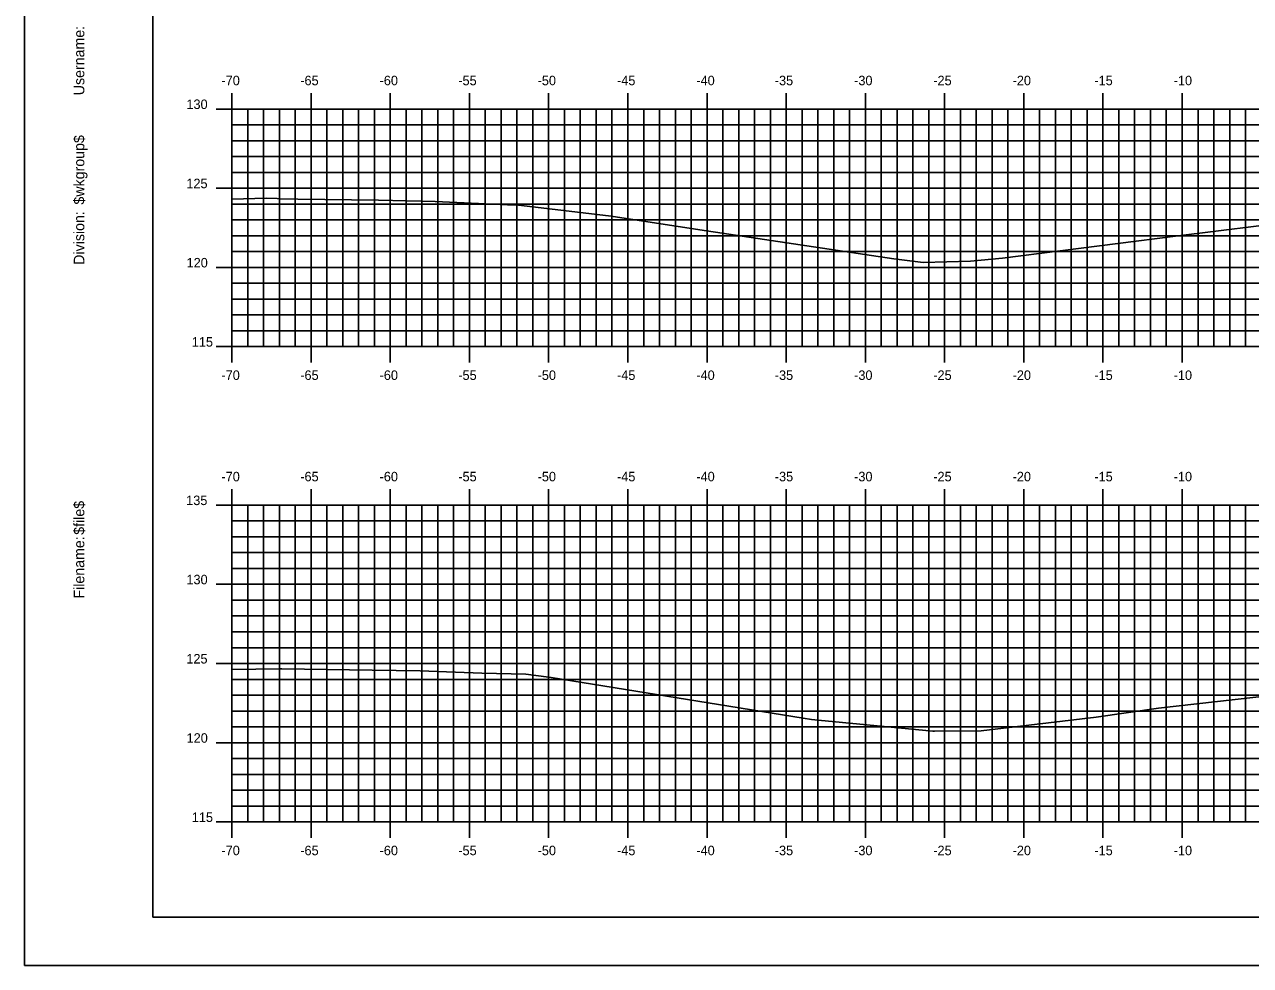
# Model space of a CAD drawing. Extents: x 852182 to 852354, y 365624 to 365734.
# Drawn here: x 852181.9 to 852259.3, y 365624 to 365683.4 of the extents above; entities that cross this region are included whole.
import ezdxf

# ---------------------------------------------------------------- set-up
doc = ezdxf.new("R2010")
doc.units = 0
for name, color, linetype in [('BORDER', 7, 'Continuous'), ('H_V ANNOTATION', 7, 'Continuous'), ('M_Roadway_Centerline', 7, 'Continuous'), ('MAJOR', 7, 'Continuous'), ('MINOR', 7, 'Continuous'), ('PLOT BOUNDARY', 7, 'Continuous'), ('S_Roadway_Centerline', 7, 'Continuous')]:
    doc.layers.add(name, color=color, linetype=linetype)

msp = doc.modelspace()

# ---------------------------------------------------------------- linework, layer by layer
at = {"layer": 'BORDER'}
msp.add_lwpolyline([(852190.035, 365627.027), (852350.035, 365627.027), (852350.035, 365732.027), (852190.035, 365732.027)], close=True, dxfattribs=at)
at = {"layer": 'MAJOR'}
for p, q in [((852195.035, 365679.029), (852195.035, 365678.027)), ((852200.035, 365679.029), (852200.035, 365678.027)), ((852205.035, 365679.029), (852205.035, 365678.027)), ((852210.035, 365679.029), (852210.035, 365678.027)), ((852215.035, 365679.029), (852215.035, 365678.027)), ((852220.035, 365679.029), (852220.035, 365678.027)), ((852225.035, 365679.029), (852225.035, 365678.027)), ((852230.035, 365679.029), (852230.035, 365678.027)), ((852235.035, 365679.029), (852235.035, 365678.027)), ((852240.035, 365679.029), (852240.035, 365678.027)), ((852245.035, 365679.029), (852245.035, 365678.027)), ((852250.035, 365679.029), (852250.035, 365678.027)), ((852255.035, 365679.029), (852255.035, 365678.027)), ((852194.033, 365678.027), (852195.035, 365678.027)), ((852195.035, 365678.027), (852335.035, 365678.027)), ((852195.035, 365663.027), (852195.035, 365678.027)), ((852195.035, 365663.027), (852195.035, 365678.027)), ((852195.035, 365678.027), (852335.035, 365678.027)), ((852200.035, 365663.027), (852200.035, 365678.027)), ((852205.035, 365663.027), (852205.035, 365678.027)), ((852210.035, 365663.027), (852210.035, 365678.027)), ((852215.035, 365663.027), (852215.035, 365678.027)), ((852220.035, 365663.027), (852220.035, 365678.027)), ((852225.035, 365663.027), (852225.035, 365678.027)), ((852230.035, 365663.027), (852230.035, 365678.027)), ((852235.035, 365663.027), (852235.035, 365678.027)), ((852240.035, 365663.027), (852240.035, 365678.027)), ((852245.035, 365663.027), (852245.035, 365678.027)), ((852250.035, 365663.027), (852250.035, 365678.027)), ((852255.035, 365663.027), (852255.035, 365678.027)), ((852194.033, 365673.027), (852195.035, 365673.027)), ((852195.035, 365673.027), (852335.035, 365673.027)), ((852194.033, 365668.027), (852195.035, 365668.027)), ((852195.035, 365668.027), (852335.035, 365668.027)), ((852194.033, 365663.027), (852195.035, 365663.027)), ((852195.035, 365663.027), (852335.035, 365663.027)), ((852195.035, 365663.027), (852335.035, 365663.027)), ((852195.035, 365662.025), (852195.035, 365663.027)), ((852200.035, 365662.025), (852200.035, 365663.027)), ((852205.035, 365662.025), (852205.035, 365663.027)), ((852210.035, 365662.025), (852210.035, 365663.027)), ((852215.035, 365662.025), (852215.035, 365663.027)), ((852220.035, 365662.025), (852220.035, 365663.027)), ((852225.035, 365662.025), (852225.035, 365663.027)), ((852230.035, 365662.025), (852230.035, 365663.027)), ((852235.035, 365662.025), (852235.035, 365663.027)), ((852240.035, 365662.025), (852240.035, 365663.027)), ((852245.035, 365662.025), (852245.035, 365663.027)), ((852250.035, 365662.025), (852250.035, 365663.027)), ((852255.035, 365662.025), (852255.035, 365663.027)), ((852195.035, 365654.029), (852195.035, 365653.027)), ((852200.035, 365654.029), (852200.035, 365653.027)), ((852205.035, 365654.029), (852205.035, 365653.027)), ((852210.035, 365654.029), (852210.035, 365653.027)), ((852215.035, 365654.029), (852215.035, 365653.027)), ((852220.035, 365654.029), (852220.035, 365653.027)), ((852225.035, 365654.029), (852225.035, 365653.027)), ((852230.035, 365654.029), (852230.035, 365653.027)), ((852235.035, 365654.029), (852235.035, 365653.027)), ((852240.035, 365654.029), (852240.035, 365653.027)), ((852245.035, 365654.029), (852245.035, 365653.027)), ((852250.035, 365654.029), (852250.035, 365653.027)), ((852255.035, 365654.029), (852255.035, 365653.027)), ((852194.033, 365653.027), (852195.035, 365653.027)), ((852195.035, 365653.027), (852335.035, 365653.027)), ((852195.035, 365633.027), (852195.035, 365653.027)), ((852195.035, 365633.027), (852195.035, 365653.027)), ((852195.035, 365653.027), (852335.035, 365653.027)), ((852200.035, 365633.027), (852200.035, 365653.027)), ((852205.035, 365633.027), (852205.035, 365653.027)), ((852210.035, 365633.027), (852210.035, 365653.027)), ((852215.035, 365633.027), (852215.035, 365653.027)), ((852220.035, 365633.027), (852220.035, 365653.027)), ((852225.035, 365633.027), (852225.035, 365653.027)), ((852230.035, 365633.027), (852230.035, 365653.027)), ((852235.035, 365633.027), (852235.035, 365653.027)), ((852240.035, 365633.027), (852240.035, 365653.027)), ((852245.035, 365633.027), (852245.035, 365653.027)), ((852250.035, 365633.027), (852250.035, 365653.027)), ((852255.035, 365633.027), (852255.035, 365653.027)), ((852194.033, 365648.027), (852195.035, 365648.027)), ((852195.035, 365648.027), (852335.035, 365648.027)), ((852194.033, 365643.027), (852195.035, 365643.027)), ((852195.035, 365643.027), (852335.035, 365643.027)), ((852194.033, 365638.027), (852195.035, 365638.027)), ((852195.035, 365638.027), (852335.035, 365638.027)), ((852194.033, 365633.027), (852195.035, 365633.027)), ((852195.035, 365633.027), (852335.035, 365633.027)), ((852195.035, 365633.027), (852335.035, 365633.027)), ((852195.035, 365632.025), (852195.035, 365633.027)), ((852200.035, 365632.025), (852200.035, 365633.027)), ((852205.035, 365632.025), (852205.035, 365633.027)), ((852210.035, 365632.025), (852210.035, 365633.027)), ((852215.035, 365632.025), (852215.035, 365633.027)), ((852220.035, 365632.025), (852220.035, 365633.027)), ((852225.035, 365632.025), (852225.035, 365633.027)), ((852230.035, 365632.025), (852230.035, 365633.027)), ((852235.035, 365632.025), (852235.035, 365633.027)), ((852240.035, 365632.025), (852240.035, 365633.027)), ((852245.035, 365632.025), (852245.035, 365633.027)), ((852250.035, 365632.025), (852250.035, 365633.027)), ((852255.035, 365632.025), (852255.035, 365633.027))]:
    msp.add_line(p, q, dxfattribs=at)
at = {"layer": 'MINOR'}
for p, q in [((852196.035, 365663.027), (852196.035, 365678.027)), ((852197.035, 365663.027), (852197.035, 365678.027)), ((852198.035, 365663.027), (852198.035, 365678.027)), ((852199.035, 365663.027), (852199.035, 365678.027)), ((852201.035, 365663.027), (852201.035, 365678.027)), ((852202.035, 365663.027), (852202.035, 365678.027)), ((852203.035, 365663.027), (852203.035, 365678.027)), ((852204.035, 365663.027), (852204.035, 365678.027)), ((852206.035, 365663.027), (852206.035, 365678.027)), ((852207.035, 365663.027), (852207.035, 365678.027)), ((852208.035, 365663.027), (852208.035, 365678.027)), ((852209.035, 365663.027), (852209.035, 365678.027)), ((852211.035, 365663.027), (852211.035, 365678.027)), ((852212.035, 365663.027), (852212.035, 365678.027)), ((852213.035, 365663.027), (852213.035, 365678.027)), ((852214.035, 365663.027), (852214.035, 365678.027)), ((852216.035, 365663.027), (852216.035, 365678.027)), ((852217.035, 365663.027), (852217.035, 365678.027)), ((852218.035, 365663.027), (852218.035, 365678.027)), ((852219.035, 365663.027), (852219.035, 365678.027)), ((852221.035, 365663.027), (852221.035, 365678.027)), ((852222.035, 365663.027), (852222.035, 365678.027)), ((852223.035, 365663.027), (852223.035, 365678.027)), ((852224.035, 365663.027), (852224.035, 365678.027)), ((852226.035, 365663.027), (852226.035, 365678.027)), ((852227.035, 365663.027), (852227.035, 365678.027)), ((852228.035, 365663.027), (852228.035, 365678.027)), ((852229.035, 365663.027), (852229.035, 365678.027)), ((852231.035, 365663.027), (852231.035, 365678.027)), ((852232.035, 365663.027), (852232.035, 365678.027)), ((852233.035, 365663.027), (852233.035, 365678.027)), ((852234.035, 365663.027), (852234.035, 365678.027)), ((852236.035, 365663.027), (852236.035, 365678.027)), ((852237.035, 365663.027), (852237.035, 365678.027)), ((852238.035, 365663.027), (852238.035, 365678.027)), ((852239.035, 365663.027), (852239.035, 365678.027)), ((852241.035, 365663.027), (852241.035, 365678.027)), ((852242.035, 365663.027), (852242.035, 365678.027)), ((852243.035, 365663.027), (852243.035, 365678.027)), ((852244.035, 365663.027), (852244.035, 365678.027)), ((852246.035, 365663.027), (852246.035, 365678.027)), ((852247.035, 365663.027), (852247.035, 365678.027)), ((852248.035, 365663.027), (852248.035, 365678.027)), ((852249.035, 365663.027), (852249.035, 365678.027)), ((852251.035, 365663.027), (852251.035, 365678.027)), ((852252.035, 365663.027), (852252.035, 365678.027)), ((852253.035, 365663.027), (852253.035, 365678.027)), ((852254.035, 365663.027), (852254.035, 365678.027)), ((852256.035, 365663.027), (852256.035, 365678.027)), ((852257.035, 365663.027), (852257.035, 365678.027)), ((852258.035, 365663.027), (852258.035, 365678.027)), ((852259.035, 365663.027), (852259.035, 365678.027)), ((852195.035, 365677.027), (852335.035, 365677.027)), ((852195.035, 365677.027), (852196.037, 365677.027)), ((852195.035, 365676.027), (852335.035, 365676.027)), ((852195.035, 365676.027), (852196.037, 365676.027)), ((852195.035, 365675.027), (852335.035, 365675.027)), ((852195.035, 365675.027), (852196.037, 365675.027)), ((852195.035, 365674.027), (852335.035, 365674.027)), ((852195.035, 365674.027), (852196.037, 365674.027)), ((852195.035, 365672.027), (852335.035, 365672.027)), ((852195.035, 365672.027), (852196.037, 365672.027)), ((852195.035, 365671.027), (852335.035, 365671.027)), ((852195.035, 365671.027), (852196.037, 365671.027)), ((852195.035, 365670.027), (852335.035, 365670.027)), ((852195.035, 365670.027), (852196.037, 365670.027)), ((852195.035, 365669.027), (852335.035, 365669.027)), ((852195.035, 365669.027), (852196.037, 365669.027)), ((852195.035, 365667.027), (852335.035, 365667.027)), ((852195.035, 365667.027), (852196.037, 365667.027)), ((852195.035, 365666.027), (852335.035, 365666.027)), ((852195.035, 365666.027), (852196.037, 365666.027)), ((852195.035, 365665.027), (852335.035, 365665.027)), ((852195.035, 365665.027), (852196.037, 365665.027)), ((852195.035, 365664.027), (852335.035, 365664.027)), ((852195.035, 365664.027), (852196.037, 365664.027)), ((852196.035, 365633.027), (852196.035, 365653.027)), ((852197.035, 365633.027), (852197.035, 365653.027)), ((852198.035, 365633.027), (852198.035, 365653.027)), ((852199.035, 365633.027), (852199.035, 365653.027)), ((852201.035, 365633.027), (852201.035, 365653.027)), ((852202.035, 365633.027), (852202.035, 365653.027)), ((852203.035, 365633.027), (852203.035, 365653.027)), ((852204.035, 365633.027), (852204.035, 365653.027)), ((852206.035, 365633.027), (852206.035, 365653.027)), ((852207.035, 365633.027), (852207.035, 365653.027)), ((852208.035, 365633.027), (852208.035, 365653.027)), ((852209.035, 365633.027), (852209.035, 365653.027)), ((852211.035, 365633.027), (852211.035, 365653.027)), ((852212.035, 365633.027), (852212.035, 365653.027)), ((852213.035, 365633.027), (852213.035, 365653.027)), ((852214.035, 365633.027), (852214.035, 365653.027)), ((852216.035, 365633.027), (852216.035, 365653.027)), ((852217.035, 365633.027), (852217.035, 365653.027)), ((852218.035, 365633.027), (852218.035, 365653.027)), ((852219.035, 365633.027), (852219.035, 365653.027)), ((852221.035, 365633.027), (852221.035, 365653.027)), ((852222.035, 365633.027), (852222.035, 365653.027)), ((852223.035, 365633.027), (852223.035, 365653.027)), ((852224.035, 365633.027), (852224.035, 365653.027)), ((852226.035, 365633.027), (852226.035, 365653.027)), ((852227.035, 365633.027), (852227.035, 365653.027)), ((852228.035, 365633.027), (852228.035, 365653.027)), ((852229.035, 365633.027), (852229.035, 365653.027)), ((852231.035, 365633.027), (852231.035, 365653.027)), ((852232.035, 365633.027), (852232.035, 365653.027)), ((852233.035, 365633.027), (852233.035, 365653.027)), ((852234.035, 365633.027), (852234.035, 365653.027)), ((852236.035, 365633.027), (852236.035, 365653.027)), ((852237.035, 365633.027), (852237.035, 365653.027)), ((852238.035, 365633.027), (852238.035, 365653.027)), ((852239.035, 365633.027), (852239.035, 365653.027)), ((852241.035, 365633.027), (852241.035, 365653.027)), ((852242.035, 365633.027), (852242.035, 365653.027)), ((852243.035, 365633.027), (852243.035, 365653.027)), ((852244.035, 365633.027), (852244.035, 365653.027)), ((852246.035, 365633.027), (852246.035, 365653.027)), ((852247.035, 365633.027), (852247.035, 365653.027)), ((852248.035, 365633.027), (852248.035, 365653.027)), ((852249.035, 365633.027), (852249.035, 365653.027)), ((852251.035, 365633.027), (852251.035, 365653.027)), ((852252.035, 365633.027), (852252.035, 365653.027)), ((852253.035, 365633.027), (852253.035, 365653.027)), ((852254.035, 365633.027), (852254.035, 365653.027)), ((852256.035, 365633.027), (852256.035, 365653.027)), ((852257.035, 365633.027), (852257.035, 365653.027)), ((852258.035, 365633.027), (852258.035, 365653.027)), ((852259.035, 365633.027), (852259.035, 365653.027)), ((852195.035, 365652.027), (852335.035, 365652.027)), ((852195.035, 365652.027), (852196.037, 365652.027)), ((852195.035, 365651.027), (852335.035, 365651.027)), ((852195.035, 365651.027), (852196.037, 365651.027)), ((852195.035, 365650.027), (852335.035, 365650.027)), ((852195.035, 365650.027), (852196.037, 365650.027)), ((852195.035, 365649.027), (852335.035, 365649.027)), ((852195.035, 365649.027), (852196.037, 365649.027)), ((852195.035, 365647.027), (852335.035, 365647.027)), ((852195.035, 365647.027), (852196.037, 365647.027)), ((852195.035, 365646.027), (852335.035, 365646.027)), ((852195.035, 365646.027), (852196.037, 365646.027)), ((852195.035, 365645.027), (852335.035, 365645.027)), ((852195.035, 365645.027), (852196.037, 365645.027)), ((852195.035, 365644.027), (852335.035, 365644.027)), ((852195.035, 365644.027), (852196.037, 365644.027)), ((852195.035, 365642.027), (852335.035, 365642.027)), ((852195.035, 365642.027), (852196.037, 365642.027)), ((852195.035, 365641.027), (852335.035, 365641.027)), ((852195.035, 365641.027), (852196.037, 365641.027)), ((852195.035, 365640.027), (852335.035, 365640.027)), ((852195.035, 365640.027), (852196.037, 365640.027)), ((852195.035, 365639.027), (852335.035, 365639.027)), ((852195.035, 365639.027), (852196.037, 365639.027)), ((852195.035, 365637.027), (852335.035, 365637.027)), ((852195.035, 365637.027), (852196.037, 365637.027)), ((852195.035, 365636.027), (852335.035, 365636.027)), ((852195.035, 365636.027), (852196.037, 365636.027)), ((852195.035, 365635.027), (852335.035, 365635.027)), ((852195.035, 365635.027), (852196.037, 365635.027)), ((852195.035, 365634.027), (852335.035, 365634.027)), ((852195.035, 365634.027), (852196.037, 365634.027))]:
    msp.add_line(p, q, dxfattribs=at)
at = {"layer": 'PLOT BOUNDARY'}
msp.add_lwpolyline([(852181.942, 365623.968), (852351.942, 365623.968), (852351.942, 365733.968), (852181.942, 365733.968)], close=True, dxfattribs=at)
at = {"layer": 'S_Roadway_Centerline'}
for points in [[(852195.035, 365672.34), (852197.217, 365672.406), (852197.892, 365672.383), (852198.04, 365672.364), (852199.2, 365672.345), (852204.3, 365672.27), (852207.88, 365672.183), (852212.442, 365671.975), (852212.967, 365671.973), (852218.989, 365671.259), (852224.573, 365670.41), (852236.839, 365668.572), (852238.688, 365668.336), (852241.679, 365668.433), (852243.687, 365668.608), (852254.618, 365670.011), (852262.427, 365670.97)], [(852195.035, 365642.644), (852196.544, 365642.668), (852198.018, 365642.695), (852198.199, 365642.683), (852203.899, 365642.613), (852206.928, 365642.565), (852210.807, 365642.423), (852213.586, 365642.348), (852215.189, 365642.148), (852231.097, 365639.581), (852231.641, 365639.502), (852232.046, 365639.445), (852239.297, 365638.761), (852239.399, 365638.751), (852242.352, 365638.783), (852249.601, 365639.633), (852253.547, 365640.203), (852260.793, 365641.02)]]:
    msp.add_lwpolyline(points, dxfattribs=at)

# ---------------------------------------------------------------- texts
at = {"layer": 'BORDER'}
for s, p in [('Username:', (852185.72, 365678.895)), ('$wkgroup$', (852185.72, 365671.996)), ('Division:', (852185.72, 365668.193)), ('$file$', (852185.72, 365651.152)), ('Filename:', (852185.72, 365647.125))]:
    msp.add_text(s, height=0.6696, rotation=90, dxfattribs=at).set_placement(p)
at = {"layer": 'H_V ANNOTATION'}
for s, p in [('-70', (852194.377, 365679.527)), ('-65', (852199.353, 365679.527)), ('-60', (852204.361, 365679.527)), ('-55', (852209.331, 365679.527)), ('-50', (852214.339, 365679.527)), ('-45', (852219.353, 365679.527)), ('-40', (852224.361, 365679.527)), ('-35', (852229.315, 365679.527)), ('-30', (852234.323, 365679.527)), ('-25', (852239.321, 365679.527)), ('-20', (852244.329, 365679.527)), ('-15', (852249.492, 365679.527)), ('-10', (852254.5, 365679.527)), ('130', (852192.165, 365678.027)), ('125', (852192.16, 365673.027)), ('120', (852192.176, 365668.027)), ('115', (852192.503, 365663.027)), ('-70', (852194.377, 365660.927)), ('-65', (852199.353, 365660.927)), ('-60', (852204.361, 365660.927)), ('-55', (852209.331, 365660.927)), ('-50', (852214.339, 365660.927)), ('-45', (852219.353, 365660.927)), ('-40', (852224.361, 365660.927)), ('-35', (852229.315, 365660.927)), ('-30', (852234.323, 365660.927)), ('-25', (852239.321, 365660.927)), ('-20', (852244.329, 365660.927)), ('-15', (852249.492, 365660.927)), ('-10', (852254.5, 365660.927)), ('-70', (852194.377, 365654.527)), ('-65', (852199.353, 365654.527)), ('-60', (852204.361, 365654.527)), ('-55', (852209.331, 365654.527)), ('-50', (852214.339, 365654.527)), ('-45', (852219.353, 365654.527)), ('-40', (852224.361, 365654.527)), ('-35', (852229.315, 365654.527)), ('-30', (852234.323, 365654.527)), ('-25', (852239.321, 365654.527)), ('-20', (852244.329, 365654.527)), ('-15', (852249.492, 365654.527)), ('-10', (852254.5, 365654.527)), ('135', (852192.149, 365653.027)), ('130', (852192.165, 365648.027)), ('125', (852192.16, 365643.027)), ('120', (852192.176, 365638.027)), ('115', (852192.503, 365633.027)), ('-70', (852194.377, 365630.927)), ('-65', (852199.353, 365630.927)), ('-60', (852204.361, 365630.927)), ('-55', (852209.331, 365630.927)), ('-50', (852214.339, 365630.927)), ('-45', (852219.353, 365630.927)), ('-40', (852224.361, 365630.927)), ('-35', (852229.315, 365630.927)), ('-30', (852234.323, 365630.927)), ('-25', (852239.321, 365630.927)), ('-20', (852244.329, 365630.927)), ('-15', (852249.492, 365630.927)), ('-10', (852254.5, 365630.927))]:
    msp.add_text(s, height=0.6, dxfattribs=at).set_placement(p)
at = {"layer": 'M_Roadway_Centerline'}
for s, p in [('C', (852197.212, 365672.406)), ('L', (852197.217, 365672.399)), ('C', (852198.013, 365642.695)), ('L', (852198.018, 365642.688))]:
    msp.add_text(s, height=0.0146, dxfattribs=at).set_placement(p)
at = {"layer": 'MAJOR'}
for p in [(852195.031, 365663.027), (852195.031, 365633.027)]:
    msp.add_text('-', height=0.006, dxfattribs=at).set_placement(p)

doc.saveas('drawing.dxf')
